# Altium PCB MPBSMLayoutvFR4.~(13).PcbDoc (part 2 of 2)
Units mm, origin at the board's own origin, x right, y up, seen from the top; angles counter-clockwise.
Board outline 131.7 x 110.39 mm, 4 copper layers (Top Layer, Power, GroundPlane, Bottom Layer), stack 2.286 mm thick; 156 components, 77 nets, 429 pads, 117 vias.
Unrouted connection lines stored in the file: 25.
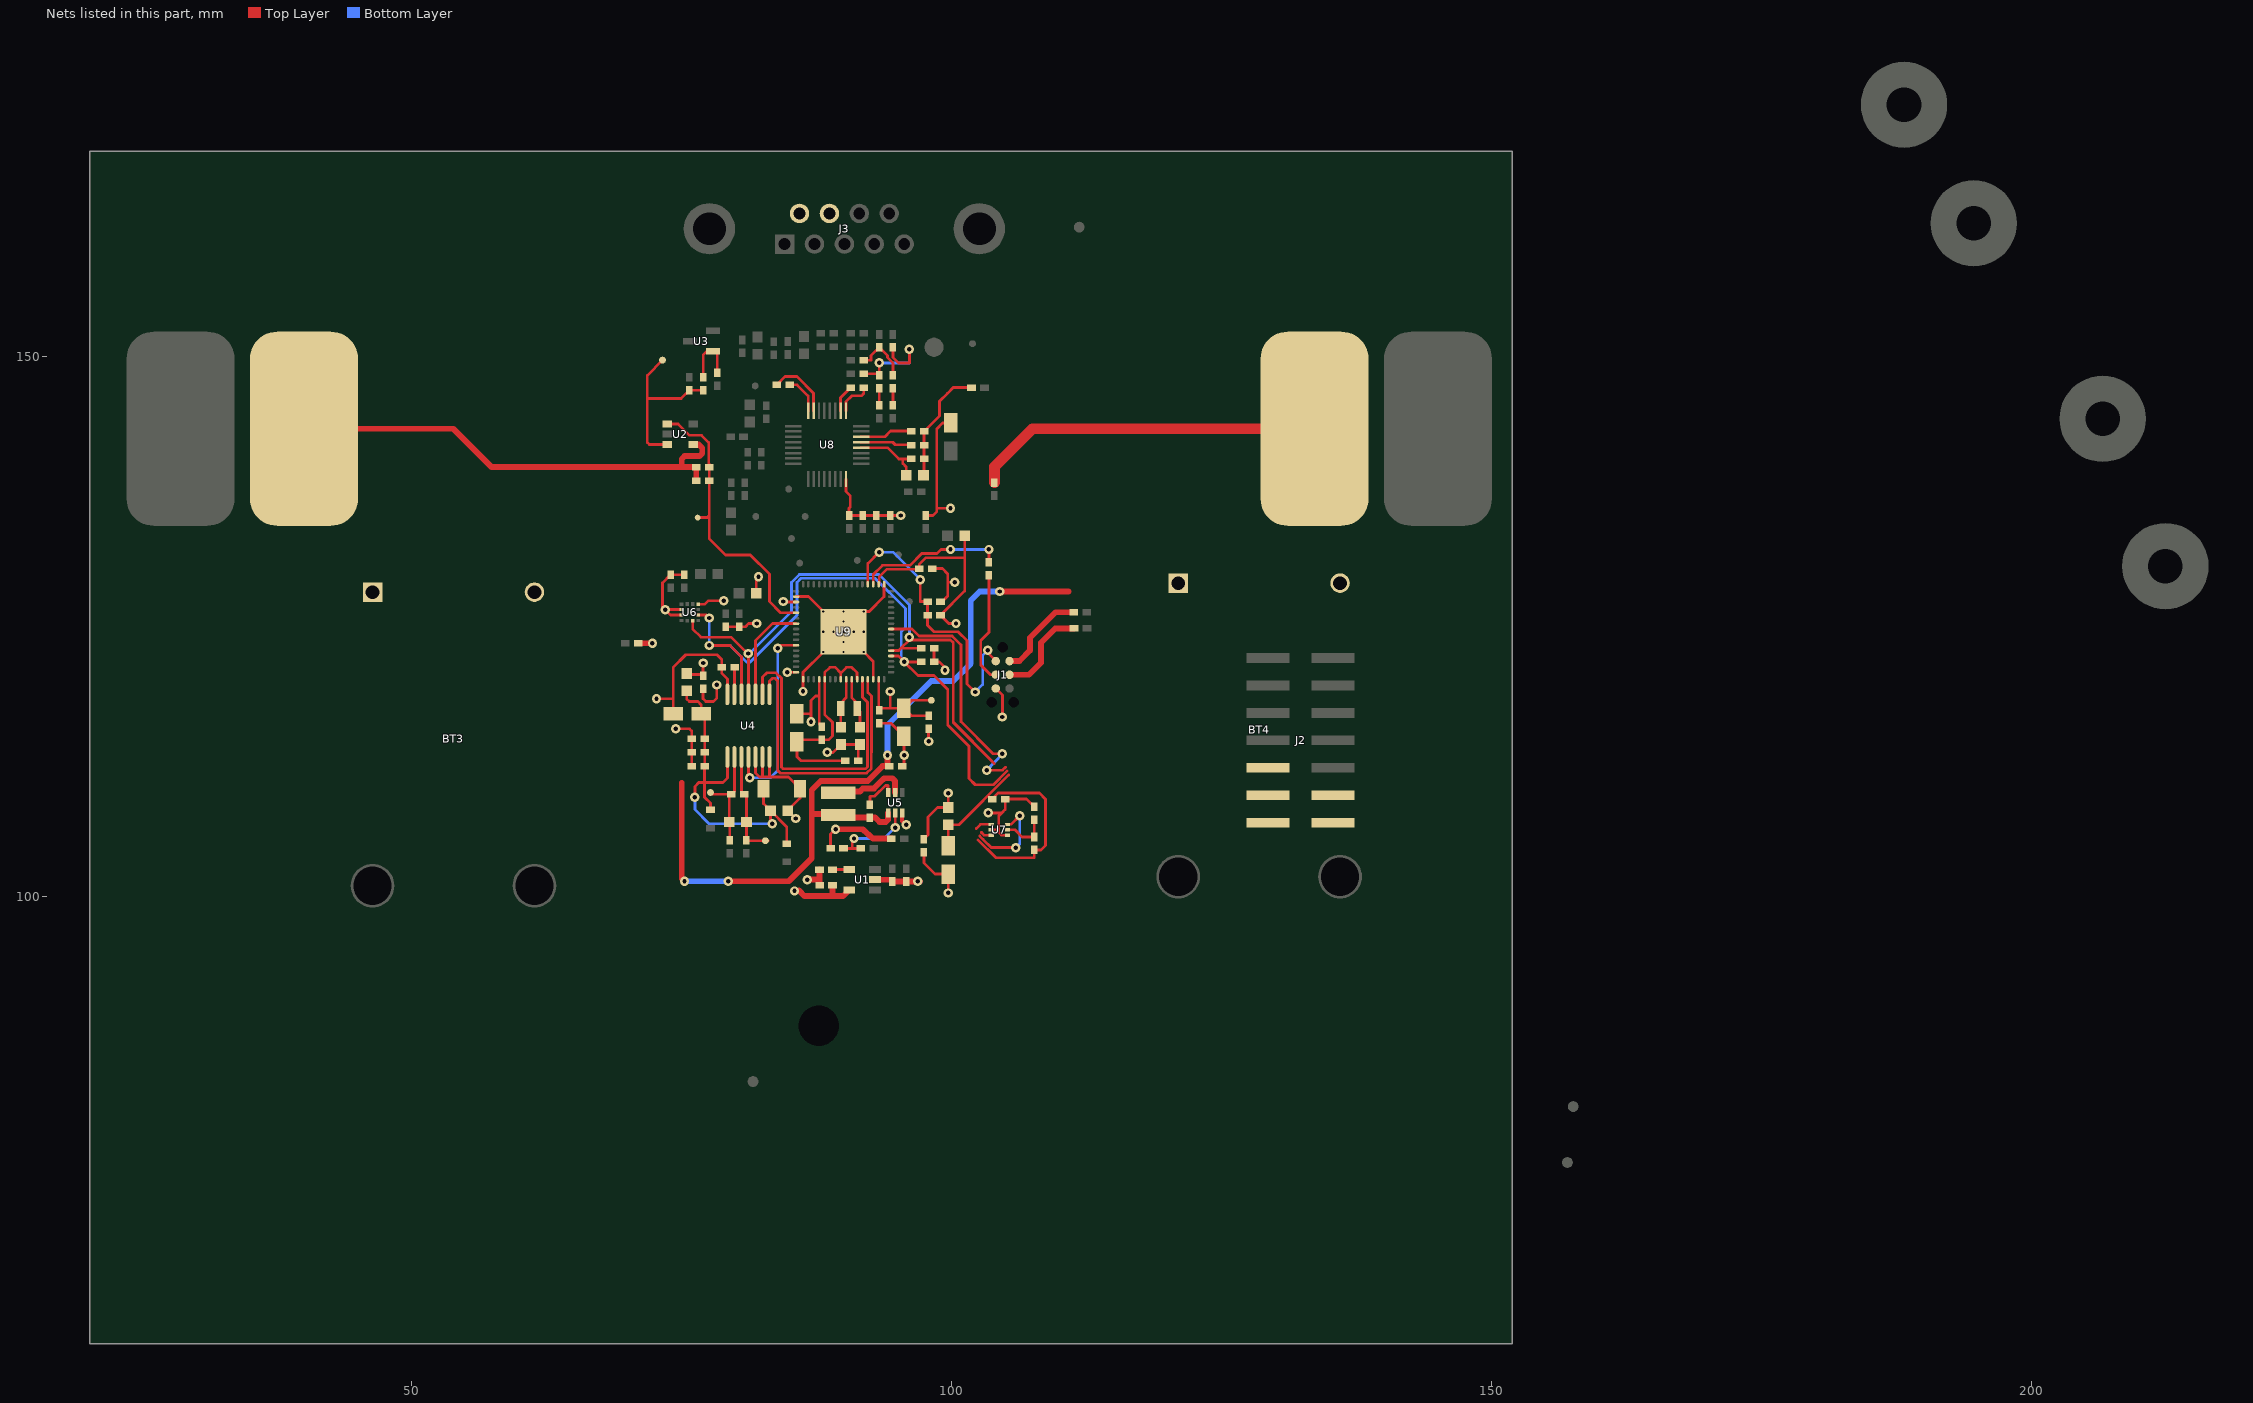
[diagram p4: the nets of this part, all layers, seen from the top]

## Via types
v1: diameter 0.864, hole 0.406, Top Layer to Bottom Layer, 104 vias
v2: diameter 0.5, hole 0.2, Top Layer to Bottom Layer, 13 vias

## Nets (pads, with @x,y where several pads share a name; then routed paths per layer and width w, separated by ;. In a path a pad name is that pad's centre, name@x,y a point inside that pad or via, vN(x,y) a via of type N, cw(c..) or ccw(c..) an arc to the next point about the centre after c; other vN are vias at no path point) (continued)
BOOST_INPUT: BT3.1 BT4.1 C34.1 L7.1 R16.1 U5.1 | length 73.3
  Top Layer w0.254: L7.1@89.536,107.681 L7.1@89.545,107.672 ; v1(94.082,113.132) v1@94.244,112.97
  Top Layer w0.5: 75.032,110.592 75.032,101.702 v1(75.286,101.448)
  Top Layer w0.54: v1(79.35,101.448) 84.938,101.448 87.071,103.581 87.071,109.906 87.909,110.744 92.253,110.744 93.624,112.116 C34.1@94.244,112.116 ; 87.071,107.696 L7.1@89.536,107.681 ; L7.1@89.755,107.35 R16.1@92.456,107.35 92.942,107.35 93.358,106.934 93.929,106.934 94.143,107.148 U5.1@94.143,107.762 ; C34.1@94.082,112.278 v1(94.082,113.132) ; v1(104.496,128.287) 110.845,128.287
  Bottom Layer w0.54: v1(75.286,101.448) v1(79.35,101.448) ; v1(94.082,113.132) 94.082,115.926 98.146,119.99 100.178,119.99 101.794,121.606 101.794,127.448 102.633,128.287 v1(104.496,128.287)
DVCC: 1.1 C1.1 C5.1 C6.1 C10.1 C14.1 C18.1 L1.1 L2.1 L3.1 L5.1 R1.1 R6.2 R31.1 R32.1 U1.5 U9.18 U9.35 U9.48 U9.63 | length 53
  Top Layer w0.254: L1.1@75.286,120.59 76.864,120.59 C10.1@76.887,120.613 ; C10.1@77.013,120.488 v1(77.013,121.666) ; L3.1@81.928,128.118 81.928,129.426 v1(82.144,129.642) ; v1@84.474,127.312 U9.35@85.618,127.312 ; v1(84.8,120.812) U9.48@85.618,120.812 ; U9.63@93.268,120.162 93.268,117.339 C6.1@93.32,117.288 ; U9.18@93.268,128.962 93.315,129.008 93.315,129.637 94.034,130.356 96.99,130.356 C18.1@97.038,130.404 97.038,130.82 97.638,131.42 101.194,131.42 ; C6.1@93.512,117.48 C1.1@95.606,117.48 ; 94.339,117.483 v1(94.339,119.027) ; C14.1@97.462,105.35 97.841,105.728 97.841,107.414 98.712,108.286 L2.1@99.703,108.286 v1(99.703,109.621) ; R1.1@97.892,116.78 96.306,116.78 C1.1@95.606,117.48 ; 1.1@98.146,118.212 96.338,118.212 C1.1@95.606,117.48 ; R32.1@98.4,123.038 R31.1@98.4,121.768 98.908,121.768 99.416,121.26 v1(99.416,121.006) ; v1(100.432,125.324) 99.762,125.324 R6.2@99,126.086 101.232,128.318 L5.1@101.232,133.452
  Top Layer w0.54: v1(85.471,100.559) v1@85.877,100.559 ; 85.903,100.584 86.411,100.076 88.997,100.076 ; C5.1@88.997,101.092 88.997,100.076 ; U1.5@90.545,100.65 89.971,100.076 88.997,100.076
  other v1: 84.43,127.356
EL_GSR1: C26.2 J3.7 R10.1 TP2.1 U2.4 | length 43.3
  Top Layer w0.254: U2.4@76.094,141.9 76.606,141.9
  Top Layer w0.54: TP2.1@40.056,143.358 53.873,143.358 57.429,139.802 R10.1@76.372,139.802 C26.2@76.372,138.532 ; 75.032,139.852 75.032,140.564 75.286,140.818 76.672,140.818 76.926,141.072 76.926,141.58 76.606,141.9
EL_GSR2: J3.6 R9.2 TP1.1 | length 32.6
  Top Layer w1: R9.2@103.988,138.37 103.988,139.827 107.518,143.358 TP1.1@133.629,143.358
GND: BT3.2 BT4.2 C1.2 C3.2 C4.2 C5.2 C6.2 C8.2 C9.2 C10.2 C11.2 C12.2 C13.2 C14.2 C15.2 C16.2 C17.2 C18.2 C19.2 C20.2 C21.2 C25.2 C27.2 C28.2 C29.1 C32.2 C33.2 C34.2 C35.2 C36.2 C37.2 C38.2 C41.2 C42.2 C58.2 C59.2 J1.6 J2.6 R2.1 R3.1 R17.1 U1.2 U4.5 U4.6 U4.7 U4.14 U5.3 U6.4 U6.8 U6.9 U7.2 U7.4 U8.24 U9.17 U9.34 U9.49 U9.62 U9.65 | length 145.9
  Top Layer w0.254: v1(72.695,118.364) 74.24,118.364 ; C9.2@74.24,116.942 74.24,118.364 ; v1(74.473,115.57) 75.743,115.57 75.956,115.357 C27.2@75.956,114.656 C11.2@75.956,113.386 C28.2@75.956,112.116 ; U6.9@75.019,126.111 73.99,126.111 v1(73.508,126.594) ; U6.8@75.019,126.611 73.525,126.611 v1(73.508,126.594) ; C37.2@75.286,129.847 C16.2@74.016,129.847 73.254,129.085 73.254,126.848 v1(73.508,126.594) ; U6.4@76.569,127.111 77.172,127.111 77.494,127.433 v1(78.914,127.433) ; C10.2@77.013,119.288 77.013,118.364 77.267,118.11 77.971,118.11 78.283,118.422 v1(78.283,119.634) ; C36.2@79.096,125.024 C17.2@80.366,125.024 80.921,125.024 81.221,125.324 v1(81.966,125.324) ; U4.14@79.26,118.764 79.26,120.193 78.75,120.704 C29.1@78.75,121.26 78.75,121.961 78.283,122.428 75.408,122.428 74.24,121.26 74.24,118.364 ; U4.5@81.86,112.964 81.86,111.484 82.245,111.1 83.16,111.1 ; 82.51,111.137 U4.6@82.51,112.964 ; U4.7@83.16,112.964 83.16,111.1 ; v1(85.594,107.266) 85.569,107.266 C33.2@84.844,107.991 85.998,109.145 C32.2@85.998,110.023 84.921,111.1 83.16,111.1 ; U9.34@85.618,127.812 86.768,127.812 v2(88.143,126.437) v2(90.018,124.562) ; v1(86.267,119.033) U9.49@86.267,120.162 86.267,120.811 v2(88.143,122.687) v2(90.018,124.562) ; v1(86.665,101.6) v1@86.677,101.613 ; v1(88.494,113.386) 89.04,113.386 89.764,114.11 C58.2@91.542,114.11 ; R17.1@88.818,104.496 88.818,105.812 v1(89.28,106.274) ; U8.24@90.244,138.704 90.244,137.544 90.626,137.162 90.626,136.099 90.526,135.999 C42.2@90.526,135.322 C41.2@91.796,135.322 C19.2@93.066,135.322 C20.2@94.336,135.322 v1@95.24,135.322 ; R2.1@91.38,112.624 C58.2@91.38,113.948 ; U9.62@92.768,120.162 92.768,121.811 v2(91.893,122.687) v2(90.018,124.562) ; C6.2@93.32,115.888 C6.2@93.32,116.088 94.398,116.088 C1.2@95.606,114.88 95.624,114.861 v1(95.624,113.132) 95.624,112.296 C34.2@95.444,112.116 C34.2@95.606,111.954 ; U9.17@93.769,128.962 93.769,127.805 92.401,126.437 v2(91.893,126.437) v2(90.018,124.562) ; C3.2@94.371,101.6 C3.2@94.544,101.428 ; v1(96.876,101.448) 96.876,101.194 v1@97.11,101.428 ; C14.2@97.462,104.15 97.462,103.147 98.488,102.122 C12.2@99.703,102.122 v1(99.703,100.374) ; C21.2@97.638,135.322 98.288,135.322 98.654,135.687 98.654,143.358 99.192,143.896 C15.2@99.924,143.896 C15.2@99.924,144.374 ; C18.2@98.238,130.404 99.162,130.404 99.67,129.896 99.67,129.134 ; 98.654,135.992 v1(99.924,135.992) ; C25.2@99,127.356 99.162,127.356 99.67,127.864 99.67,129.134 ; v1(100.305,129.134) 99.67,129.134 ; v1(103.424,107.783) 104.669,107.783 ; U7.2@103.703,106.221 104.373,106.221 ; J1.6@104.115,119.304 104.724,118.694 104.724,116.688 v1(104.699,116.662) ; U7.4@105.203,105.721 104.648,105.721 104.398,105.971 104.398,107.512 104.669,107.783 ; C38.2@107.681,108.352 106.965,109.068 C13.2@104.979,109.068 104.979,108.093 104.669,107.783
  Top Layer w0.354: U5.3@95.443,107.762 95.443,107.046 v1(95.809,106.68)
  Top Layer w0.54: R3.1@71.018,123.489 v1(72.321,123.489) ; v1@86.677,101.613 87.797,101.613 ; C5.2@87.797,101.092 87.797,101.613 ; C8.2@87.797,102.54 87.797,101.613 ; v1(89.28,106.274) 90.596,106.274 91.796,106.274 92.761,105.41 C35.2@94.497,105.41 ; U1.2@92.945,101.6 C3.2@94.371,101.6 ; C3.2@94.544,101.428 C4.2@95.814,101.428 v1@97.11,101.428
  other v1: 95.301,135.322
  other v2: 90.018,122.687 90.018,123.624 88.143,124.562 89.08,124.562 90.955,124.562 91.893,124.562 90.018,125.499 90.018,126.437
GSR_ANALOG_OUTPUT: 2.1 C26.1 R10.2 U2.1 U9.37 | length 26.9
  Top Layer w0.254: U2.1@73.694,143.8 74.7,143.8 75.752,142.748 76.869,142.748 77.53,142.088 77.53,140.14 77.572,140.098 R10.2@77.572,139.802 C26.1@77.572,138.532 77.572,135.23 ; 2.1@76.505,135.128 77.47,135.128 ; 77.47,135.23 77.572,135.23 ; U9.37@85.618,126.312 84.204,126.312 83.16,127.356 83.16,129.896 81.382,131.674 79.096,131.674 77.572,133.198 77.572,135.23
JTAG_TCK: J1.4 J2.4 R7.1 | length 10.4
  Top Layer w0.254: R7.1@103.48,129.804 103.48,124.511 102.718,123.749 102.718,121.463 103.607,120.574 J1.4@104.115,120.574
JTAG_TDO/TDI: C25.1 J1.2 J2.2 R6.1 U9.20 | length 28.1
  Top Layer w0.254: U9.20@92.268,128.962 92.268,130.876 v1(93.32,131.928) ; v1(97.13,129.388) 97.13,127.356 C25.1@97.8,127.356 R6.1@97.8,126.086 97.8,125.162 98.4,124.562 100.626,124.562 101.448,123.74 101.448,119.736 v1(102.21,118.974) ; v1(103.378,122.843) 103.378,122.58 J1.2@104.115,121.844
  Bottom Layer w0.254: v1(93.32,131.928) 94.59,131.928 v1(97.13,129.388) ; v1(102.21,118.974) 102.895,119.659 102.895,122.36 v1(103.378,122.843)
JTAG_TEST/SBWTCK: R7.2 U9.19 | length 13.7
  Top Layer w0.254: U9.19@92.768,128.962 92.768,129.852 93.626,130.71 96.166,130.71 97.257,131.801 98.652,131.801 99.033,132.182 v1(99.924,132.182) ; R7.2@103.48,131.004 v1(103.48,132.182)
  Bottom Layer w0.254: v1(99.924,132.182) v1(103.48,132.182)
JTAG_VCC_TARGET_IN: J1.3 J2.3 R5.1 | length 8.8
  Top Layer w0.54: J1.3@105.385,120.574 107.188,120.574 108.306,121.691 108.306,122.707 108.306,123.546 109.621,124.861 R5.1@111.357,124.861
JTAG_VCC_TOOL_OUT: J1.1 J2.1 R4.1 | length 8.5
  Top Layer w0.54: J1.1@105.385,121.844 106.299,121.844 107.29,122.834 107.29,124.003 109.652,126.365 R4.1@111.338,126.365
MSP_AVCC: C2.1 C7.1 R1.2 U9.52 | length 9.3
  Top Layer w0.254: C2.1@86.019,116.972 87,116.972 ; v1(87,116.21) 87,116.972 ; C7.1@87.767,115.982 87.767,118.618 ; U9.52@87.767,120.162 87.767,118.618 ; v1(97.892,114.402) R1.2@97.892,115.58 ; 87,116.972 87,118.191 87.427,118.618 87.767,118.618
MSP_AVSS: C2.2 C7.2 R2.2 U9.53 U9.56 U9.59 | length 20.5
  Top Layer w0.254: C2.2@85.7,114.372 85.7,112.979 86.055,112.624 R2.2@90.18,112.624 ; C2.2@85.892,114.564 C7.2@87.986,114.564 88.656,114.564 89.002,114.91 89.002,116.18 88.267,116.914 U9.53@88.267,120.162 88.267,120.779 88.748,121.26 89.256,121.26 89.76,120.756 ; U9.56@89.768,120.162 89.768,120.756 90.272,121.26 90.78,121.26 91.268,120.771 U9.59@91.268,120.162
MSP_LFXIN: C59.1 U9.57 Y1.1 | length 4.1
  Top Layer w0.254: C59.1@89.764,115.71 89.764,117.438 Y1.1@89.776,117.45 ; Y1.1@89.776,117.97 90.268,118.462 U9.57@90.268,120.162
MSP_LFXOUT: C58.1 U9.58 Y1.2 | length 4.3
  Top Layer w0.254: U9.58@90.768,120.162 90.768,118.477 Y1.2@91.276,117.97 ; Y1.2@91.276,117.45 91.542,117.184 C58.1@91.542,115.71
MSP_P1.0_INT: U4.10 U9.39 | length 9.4
  Top Layer w0.254: U4.10@81.86,118.764 81.86,123.749 ; 81.876,123.749 83.439,125.312 U9.39@85.618,125.312
MSP_P2.7_INT: U7.3 U9.9 | length 24.2
  Top Layer w0.254: U9.9@94.418,124.812 96.341,124.812 96.999,124.154 100.078,124.154 100.886,123.346 100.886,116.234 103.861,113.259 v1(104.724,113.259) ; 102.765,105.989 103.033,105.721 U7.3@103.703,105.721 ; v1@103.284,111.743 104.745,111.743 105.014,112.011
  Bottom Layer w0.254: v1(103.276,111.735) v1(104.724,113.259)
MSP_P4.0_INT: U4.9 U9.60 | length 28.4
  Top Layer w0.254: U4.9@82.51,118.764 82.51,120.356 82.906,120.752 83.772,120.752 84.276,120.248 84.276,112.016 84.43,111.862 92.05,111.862 92.234,112.046 92.234,113.506 92.244,113.516 92.244,114.704 92.234,114.713 92.234,115.106 92.244,115.116 92.244,116.304 92.234,116.313 92.234,118.027 91.768,118.493 U9.60@91.768,120.162
MSP_P4.1_INT: U4.8 U9.61 | length 27.8
  Top Layer w0.254: U4.8@83.16,118.764 83.16,119.99 83.414,120.244 83.668,120.244 83.922,119.99 83.922,111.718 84.186,111.454 92.15,111.454 ; 92.15,111.461 92.588,111.9 92.588,113.36 92.598,113.369 92.598,118.612 92.268,118.942 U9.61@92.268,120.162
MSP_P9.3_OUT: U4.4 U9.43 | length 18
  Top Layer w0.254: U4.4@81.21,112.964 81.21,111.169 v1(81.331,111.049) ; v1(83.922,123.038) 84.196,123.312 U9.43@85.618,123.312
  Bottom Layer w0.254: v1(81.331,111.049) 83.253,111.049 83.922,111.718 v1(83.922,123.038)
MSP_UCB0SCL_TMP103_SCL_RF430CL330HCPW_SCL: R32.2 U4.11 U6.12 U7.1 U9.5 | length 56.8
  Top Layer w0.254: U6.12@76.044,125.586 76.044,124.82 76.81,124.054 79.604,124.054 v1@81.16,122.497 ; U4.11@81.21,118.764 v1@81.21,122.447 ; U9.5@94.418,122.812 95.126,122.812 95.352,123.038 ; v1(96.114,124.054) v1@96.114,123.8 ; R32.2@97.038,123.038 95.352,123.038 ; 102.314,106.343 102.692,106.721 U7.1@103.703,106.721 ; 103.967,112.365 103.785,112.547 100.178,116.18 100.178,123.546 99.924,123.8 v1@96.114,123.8 ; 95.352,123.038 v1@96.114,123.8
  Bottom Layer w0.254: v1(81.202,122.539) 81.21,122.531 81.21,122.447 85.192,126.428 85.192,129.134 85.924,129.866 93.289,129.866 96.114,127.042 v1(96.114,124.054)
MSP_UCB0SDA_TMP103_SDA_RF430CL330HCPW_SDA: R31.2 U4.12 U6.2 U7.6 U9.4 | length 70.6
  Top Layer w0.254: U6.2@76.569,126.111 77.292,126.111 v1(77.572,125.832) ; v1(77.572,123.292) 79.518,123.292 80.577,122.233 80.577,118.78 U4.12@80.56,118.764 ; U9.4@94.418,122.312 95.098,122.312 v1(95.642,121.768) ; R31.2@97.2,121.768 v1(95.642,121.768) ; 102.618,105.635 102.921,105.332 102.929,105.332 103.691,104.57 v1(105.977,104.57) ; 105.16,111.657 103.892,110.388 102.21,110.388 101.638,110.96 101.638,113.957 99.67,115.926 99.67,119.228 98.4,120.498 96.912,120.498 v1(95.642,121.768) ; U7.6@105.203,106.721 105.537,106.721 v1(106.332,107.516)
  Bottom Layer w0.254: v1(77.572,125.832) v1(77.572,123.292) 79.518,123.292 81.042,121.768 81.382,121.768 85.7,126.086 85.7,129.134 86.078,129.512 92.941,129.512 95.76,126.694 95.76,124.97 95.352,124.562 95.352,122.058 v1(95.642,121.768) ; v1(105.977,104.57) 106.332,104.925 v1(106.332,107.516)
Net3_1: 3.1 R11.1 R12.2 U2.3 | length 15.6
  Top Layer w0.254: 71.846,146.152 74.983,146.152 R12.2@75.748,146.917 R11.1@77.018,146.917 ; 3.1@73.254,149.708 71.846,148.3 71.846,142.088 72.034,141.9 U2.3@73.694,141.9
Net4_1: 4.1 C30.1 C31.1 R13.1 U4.2 | length 9.9
  Top Layer w0.254: 4.1@77.694,109.676 77.855,109.515 C31.1@79.634,109.515 ; R13.1@79.472,105.255 79.472,106.903 C30.1@79.434,106.941 79.434,109.315 C31.1@79.634,109.515 ; U4.2@79.91,112.964 79.91,109.791 C31.1@79.634,109.515
Net5_1: 5.1 C30.2 C31.2 R14.1 U4.3 | length 9.9
  Top Layer w0.254: U4.3@80.56,112.964 80.56,109.788 C31.2@80.834,109.515 81.034,109.315 C30.2@81.034,106.941 81.034,105.293 81.131,105.197 5.1@83.028,105.197
NetC8_1: C8.1 U1.4 | length 1.6
  Top Layer w0.254: C8.1@88.992,102.54 89.002,102.55 U1.4@90.545,102.55
NetC29_2: C29.2 U4.13 | length 2.5
  Top Layer w0.254: U4.13@79.91,118.764 79.91,121.22 C29.2@79.95,121.26
NetC38_1: C38.1 R18.1 U7.5 | length 4.3
  Top Layer w0.254: U7.5@105.203,106.221 105.875,106.221 106.538,105.558 R18.1@107.681,105.558 C38.1@107.681,107.152
NetC43_1: C43.1 R19.2 R20.2 R21.2 R22.1 | length 10.9
  Top Layer w0.254: C43.1@97.476,139.094 R20.2@97.476,140.564 R21.2@97.476,141.834 97.476,141.876 R19.2@97.476,143.104 98.908,144.536 98.908,145.898 99.628,146.618 100.178,147.168 R22.1@101.864,147.168
NetC43_2: C43.2 R20.1 U8.28 | length 6.7
  Top Layer w0.254: U8.28@91.643,141.603 94.096,141.603 95.136,140.564 95.504,140.564 ; C43.2@95.822,139.04 95.822,139.818 95.504,140.135 95.504,140.564 ; R20.1@96.276,140.564 95.504,140.564
NetC45_1: C45.1 U8.2 | length 2.6
  Top Layer w0.254: U8.2@89.744,145.003 89.744,146.224 C45.1@90.688,147.168
NetC45_2: C45.2 U8.1 | length 3.4
  Top Layer w0.254: U8.1@90.244,145.003 90.244,145.87 90.78,146.406 91.681,146.406 91.888,146.612 C45.2@91.888,147.168
NetC46_2: C46.2 C48.2 C49.2 | length 10.4
  Top Layer w0.254: C46.2@91.888,148.45 C49.2@93.191,148.45 ; C49.2@93.32,148.322 v1(93.32,149.454) ; C48.2@94.59,150.886 94.595,150.88 94.595,149.967 95.109,149.454 96.114,149.454 v1(96.114,150.724)
  Bottom Layer w0.254: v1(93.32,149.454) 96.114,149.454 v1(96.114,150.724)
NetC47_1: C47.1 U8.8 | length 3.5
  Top Layer w0.254: C47.1@85.03,147.422 85.7,147.422 86.744,146.378 U8.8@86.744,145.003
NetC47_2: C47.2 U8.7 | length 6
  Top Layer w0.254: C47.2@83.83,147.422 84.592,148.184 85.7,148.184 87.244,146.64 U8.7@87.244,145.003
NetC49_1: C49.1 R26.1 | length 1.6
  Top Layer w0.254: R26.1@93.32,145.528 C49.1@93.32,147.122
NetC52_2: C52.2 C53.2 C54.2 | length 5.3
  Top Layer w0.254: C54.2@91.888,149.708 92.558,149.708 92.558,150.124 C52.2@93.32,150.886 94.082,150.124 94.082,149.962 94.59,149.454 C53.2@94.59,148.322
NetC53_1: C53.1 R27.1 | length 1.6
  Top Layer w0.254: R27.1@94.59,145.528 C53.1@94.59,147.122
NetL7_2: L7.2 U5.5 | length 5.5
  Top Layer w0.254: 92.862,110.033 92.862,110.084
  Top Layer w0.54: L7.2@90.983,109.752 91.515,109.752 91.796,110.033 92.862,110.033 ; 92.862,110.084 93.443,110.664 93.777,110.998 94.539,110.998 94.793,110.744 U5.5@94.793,109.662
NetR8_1: R8.1 R11.2 U3.1 | length 5.5
  Top Layer w0.254: R11.2@77.018,148.117 77.018,150.17 77.384,150.536 78.334,150.536 R8.1@78.334,148.53
NetR15_1: R15.1 R17.2 U5.2 | length 8.1
  Top Layer w0.254: R17.2@90.018,104.496 90.815,104.496 ; v1(90.983,105.41) 90.815,105.242 90.815,104.496 ; R15.1@91.612,104.496 90.815,104.496 ; v1(94.793,106.426) U5.2@94.793,107.762
  Bottom Layer w0.254: v1(90.983,105.41) 93.777,105.41 v1(94.793,106.426)
NetR16_2: R16.2 U5.6 | length 3.5
  Top Layer w0.254: R16.2@92.456,108.55 92.456,109.271 92.507,109.322 92.888,109.322 93.893,110.327 94.132,110.327 94.132,109.672 U5.6@94.143,109.662
NetR19_1: R19.1 U8.30 | length 4.9
  Top Layer w0.254: U8.30@91.643,142.603 93.835,142.603 94.378,143.146 R19.1@96.276,143.146
NetR21_1: R21.1 U8.29 | length 4.7
  Top Layer w0.254: U8.29@91.643,142.103 94.574,142.103 94.802,141.876 R21.1@96.276,141.876
RF430_DVCC: C9.1 C11.1 C27.1 C28.1 C32.1 C33.1 D1.1 D2.1 L1.2 U4.1 | length 34
  Top Layer w0.254: 75.489,118.512 75.489,118.338 75.735,118.092 76.523,118.092 76.84,117.775 C9.1@76.84,116.942 C9.1@77.064,117.166 ; v1(76.251,109.22) 76.251,110.236 76.606,110.592 77.15,110.592 ; C28.1@77.156,112.116 C11.1@77.156,113.386 C27.1@77.156,114.656 C9.1@77.156,116.626 ; C28.1@77.247,112.024 77.15,111.926 77.15,110.592 ; D1.1@77.694,108.079 77.694,108.691 77.15,109.235 77.15,110.592 ; U4.1@79.26,112.964 79.26,111.01 78.842,110.592 77.15,110.592 ; C32.1@82.598,110.023 82.598,108.637 C33.1@83.244,107.991 ; v1(83.414,106.782) 83.244,106.951 C33.1@83.244,107.991 ; D2.1@84.76,104.989 84.76,106.475 C33.1@83.244,107.991
  Bottom Layer w0.254: v1(76.251,109.22) 76.251,108.102 77.572,106.782 v1(83.414,106.782)
TMP_DVCC: C12.1 C13.1 L2.2 R18.2 | length 27
  Top Layer w0.254: C12.1@99.703,104.722 L2.2@99.703,106.686 100.69,106.686 105.307,111.303 ; 102.472,105.281 104.123,103.63 107.681,103.63 R18.2@107.681,104.358 108.305,104.358 108.715,104.768 108.715,109.049 108.147,109.618 104.329,109.618 C13.1@103.779,109.068
pads on no net: BT3.3 BT3.4 BT4.3 BT4.4 FID1.1 FID2.1 FID3.1 H1.0 H2.0 H3.0 H4.0 H5.1 H6.1 H7.1 H8.1 H9.0 H10.0 H11.0 H12.0 J1.5 J1.MH1 J1.MH2 J1.MH3 J2.5 J2.7 J2.8 J2.9 J2.10 J2.11 J2.12 J2.13 J2.14 J3.3 J3.5 J3.8 J3.9 U3.3 U6.10 U8.17 U9.1 U9.2 U9.3 U9.6 U9.7 U9.8 U9.10 U9.11 U9.12 U9.13 U9.15 U9.21 U9.22 U9.23 U9.24 U9.36 U9.40 U9.41 U9.42 U9.44 U9.45 U9.46 U9.47 U9.50 U9.51 U9.54 U9.55 U9.64
copper on no net: | length 0.5
  Top Layer w0.254: 104.445,124.206 v1(104.445,124.714)

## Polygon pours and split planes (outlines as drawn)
DVCC on Power (split plane): 102.334,142.288 102.334,131.727 101.699,131.092 78.59,131.092 77.955,131.727 77.955,133.144 79.149,134.338 93.066,134.338 93.115,134.348 93.157,134.376 98.237,139.456 98.265,139.498 98.275,139.548 98.275,142.796 98.684,143.205 101.417,143.205
DVCC on Power (split plane): 87.51,117.065 87.856,116.61 87.856,112.624 87.866,112.574 87.894,112.532 87.936,112.504 87.986,112.494 95.952,112.494 96.001,112.504 96.043,112.532 96.967,113.456 96.995,113.498 97.005,113.548 97.005,115.796 98.768,115.796 98.768,115.57 98.768,113.937 98.308,113.477 97.031,112.2 96.568,111.737 86.727,111.737 86.083,112.41 86.083,116.653 86.498,117.089
DVCC on Power (split plane): 90.65,154.534 90.609,146.998 81.89,147.043 81.865,147.038 81.841,147.033 81.84,147.033 81.819,147.019 81.799,147.006 81.798,147.005 81.784,146.984 81.77,146.964 81.77,146.963 81.765,146.939 81.76,146.914 81.76,143.104 81.77,143.054 81.798,143.012 81.84,142.984 81.89,142.974 86.586,142.974 86.586,141.201 83.414,141.201 83.364,141.191 83.322,141.163 83.294,141.121 83.284,141.072 83.284,135.359 77.142,135.359 77.142,139.09 77.132,139.14 77.104,139.182 74.907,141.379 74.907,145.59 77.924,148.607 79.063,148.607 79.087,148.612 79.112,148.616 79.112,148.617 79.133,148.631 79.154,148.644 79.154,148.645 79.168,148.665 79.182,148.686 79.182,148.687 79.187,148.711 79.192,148.736 79.224,154.658 90.65,154.658
DVCC on Power (split plane): 151.407,158.471 151.407,59.159 20.729,59.159 20.729,168.527 151.407,168.527
ADS_AVSS on GroundPlane (split plane): 151.407,158.471 151.407,128.806 102.085,128.806 102.085,137.008 102.075,137.057 102.047,137.099 102.005,137.127 101.956,137.137 98.908,137.137 98.858,137.127 98.816,137.099 98.788,137.057 98.778,137.008 98.778,135.765 96.446,135.765 96.446,136.398 96.436,136.448 96.408,136.49 96.366,136.518 96.317,136.527 89.378,136.527 89.362,136.524 89.347,136.524 89.338,136.52 89.328,136.518 89.315,136.509 89.301,136.503 77.631,127.993 20.729,128.018 20.729,168.527 151.407,168.527
GND on GroundPlane (split plane): 101.826,128.676 101.836,128.627 101.864,128.585 101.906,128.557 101.956,128.547 151.407,128.547 151.407,59.159 20.729,59.159 20.729,127.759 77.673,127.734 77.723,127.744 77.765,127.772 77.768,127.776 77.784,127.784 89.42,136.269 96.187,136.269 96.187,135.636 96.197,135.586 96.225,135.544 96.267,135.516 96.317,135.507 98.908,135.507 98.957,135.516 98.999,135.544 99.027,135.586 99.037,135.636 99.037,136.878 101.826,136.878

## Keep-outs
Keep-Out Layer:
  text ".Layer_Name" at 157.226,108.306 h1.52

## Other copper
Top Layer:
  text ".Layer_Name" at 157.226,156.566 h1.52
Bottom Layer:
  text ".Layer_Name" at 157.226,154.026 h1.52
  text "SVN:" at 49.644,114.91 h1.52 r90
  text ".VersionControl_RevNumber" at 49.644,107.823 h1.52 r90
  text "UL94V-0" at 55.677,69.774 h1.52 r90
Power (plane layer: these items are gaps in the copper):
  rectangle: 74.778,69.952 100.178,99.67
  lines w0.254: 98.898,115.57 98.898,115.926 ; 98.898,115.926 98.494,115.926 96.876,115.926 96.876,113.548 95.952,112.624 88.205,112.624 87.986,112.624 87.986,116.654 87.576,117.193 86.444,117.219 85.954,116.705 85.954,112.358 86.672,111.608 92.14,111.608 96.622,111.608 97.122,112.108 98.4,113.386 98.898,113.884 98.898,115.926 ; 74.778,141.326 77.013,139.09 77.013,135.23 81.186,135.23 83.414,135.23 83.414,141.072 86.716,141.072 86.716,143.104 81.89,143.104 81.89,146.914 90.738,146.868 90.78,154.534 90.78,154.788 79.096,154.788 79.063,148.736 77.87,148.736 74.778,145.644 74.778,141.326 ; 77.826,131.674 77.826,133.198 79.096,134.468 93.066,134.468 98.146,139.548 98.146,142.85 98.63,143.334 101.471,143.334 102.464,142.342 102.464,131.674 101.752,130.962 78.537,130.962 77.826,131.674
GroundPlane (plane layer: these items are gaps in the copper):
  rectangle: 74.778,69.952 100.178,99.67
  lines w0.254: 20.041,127.889 77.673,127.864 ; 77.707,127.888 89.378,136.398 96.317,136.398 96.317,135.636 98.908,135.636 98.908,137.008 101.956,137.008 101.956,128.676 151.714,128.676

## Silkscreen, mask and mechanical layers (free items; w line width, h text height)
Top Overlay:
  region: 96.317,77.724 96.317,85.344 93.777,85.344 93.777,77.724
  lines w1: 73.863,70.891 100.99,70.891 100.99,98.222 73.863,98.222 73.863,70.891
  lines w2: 20.93,133.325 44.729,133.325 150.241,133.325 ; 48.92,60.96 48.92,132.918 48.92,167.716 ; 125.628,61.646 125.628,167.157
  text "GSR" at 130.048,153.289 h4
  text "ECG" at 141.427,153.238 h4
  text "ECG" at 24.689,152.806 h4
  text "GSR" at 37.338,152.756 h4
  text "GND" at 46.584,131.318 h1.02
  text "VCC" at 60.096,129.845 h1.02
  text ".Layer_Name" at 157.226,128.626 h1.52
  text "JTAG" at 106.731,126.009 h1.02
  text "BAT" at 110.541,122.987 h1.02
  text "VCC" at 61.976,121.361 h1.02
  text "GND" at 46.838,121.158 h1.02
  text "FOR DEMO PURPOSES ONLY" at 76.479,94.259 h1.02
  text "MPBSM" at 80.061,91.44 h1.02
  text "REV A" at 80.061,89.916 h1.02
  text "TI" at 92.151,87.884 h1.52
  text "©" at 94.793,87.63 h2.67
  text ".CopyrightYear" at 85.141,77.724 h1.52
  text "MADE IN U.S." at 78.791,75.438 h1.52
  text "NFC Antenna" at 80.543,68.504 h2
  text "-" at 50.901,67.666 h1.52 r90
  text "Place phone here" at 52.908,62.84 h10
Bottom Overlay:
  text ".Layer_Name" at 157.226,126.086 h1.52
Top Paste:
  text ".Layer_Name" at 157.226,123.546 h1.52
Bottom Paste:
  text ".Layer_Name" at 157.226,121.006 h1.52
Top Solder:
  text ".Layer_Name" at 157.226,118.466 h1.52
  text ".Layer_Name" at 157.226,115.926 h1.52
Bottom Solder:
  text ".Layer_Name" at 157.226,113.386 h1.52
Drill Guide:
  text ".Layer_Name" at 157.226,110.846 h1.52
M1 Board Outline:
  lines w0.254: 75.286,58.257 101.575,58.257
  text ".Layer_Name" at 157.226,151.486 h1.52
M2 Board Dimensions:
  rectangle: 17.577,32.982 20.752,36.157
  rectangle: 20.752,29.807 30.277,32.982
  lines w0.178: 17.577,32.982 42.977,32.982 ; 20.752,29.807 20.752,36.157 ; 23.927,29.807 23.927,36.157 ; 30.277,29.807 30.277,36.157 ; 36.627,29.807 36.627,36.157 ; 17.577,29.807 42.977,29.807 42.977,36.157 17.577,36.157 17.577,29.807
  text ".Layer_Name" at 18.034,37.338 h1.52
M3 3D STEP Top:
  text ".Layer_Name" at 157.226,148.946 h1.52
M4 3D STEP Bottom:
  text ".Layer_Name" at 157.226,146.406 h1.52
M5 Assembly Top:
  lines w0.254: 10.16,16.607 177.8,16.607 ; 10.16,21.772 177.851,21.772 ; 10.16,26.937 10.16,11.443 111.887,11.443 177.851,11.443 177.851,26.937 10.173,26.937 10.173,11.443 50.19,11.443 ; 72.771,11.443 72.771,26.937 ; 104.953,21.772 104.953,26.937 ; 126.289,21.772 126.289,26.937 ; 142.088,11.278 142.088,16.43
  text "COMPONENTS MARKED 'DNP' SHOULD NOT BE POPULATED." at 46.876,32.144 h1.52
  text "ASSEMBLY VARIANT:" at 46.863,29.21 h1.52
  text ".VariantName" at 73.177,29.21 h1.52
  text "PCB VIEWED FROM TOP SIDE" at 11.773,23.58 h1.52
  text "BOARD #:" at 74.676,23.58 h1.52
  text ".PRJ_Number" at 88.532,23.58 h1.52
  text "REV:" at 109.982,23.58 h1.52
  text ".PCB_Rev" at 117.386,23.58 h1.52
  text "SVN REV:" at 131.267,23.58 h1.52
  text ".VersionControl_RevNumber" at 144.12,23.58 h1.52
  text "IGNORE ->" at 11.773,18.428 h1.52
  text "PLOT NAME =" at 11.773,13.199 h1.52
  text ".plot_File_Name" at 32.233,13.199 h1.52
  text "GENERATED    :" at 74.727,13.199 h1.52
  text ".Print_Date" at 96.812,13.199 h1.52
  text ".Print_Time" at 115.329,13.199 h1.52
  text "TEXAS INSTRUMENTS" at 147.447,13.199 h1.52
M6 Assembly Bottom:
  lines w0.254: 10.147,21.759 177.838,21.759 ; 10.198,16.595 177.838,16.595 ; 45.91,11.265 45.91,16.417 ; 61.709,21.759 61.709,26.924 ; 83.045,21.759 83.045,26.924 ; 115.227,11.43 115.227,26.924 ; 137.808,11.43 177.825,11.43 177.825,26.924 10.147,26.924 10.147,11.43 76.111,11.43 177.838,11.43 177.838,26.924
  text "COMPONENTS MARKED 'DNP' SHOULD NOT BE POPULATED." at 172.568,32.156 h1.52
  text ".VariantName" at 146.05,29.21 h1.52
  text "ASSEMBLY VARIANT:" at 172.441,29.21 h1.52
  text ".VersionControl_RevNumber" at 43.878,23.567 h1.52
  text "SVN REV:" at 56.731,23.567 h1.52
  text ".PCB_Rev" at 70.612,23.567 h1.52
  text "REV:" at 78.016,23.567 h1.52
  text ".PRJ_Number" at 99.466,23.567 h1.52
  text "BOARD #:" at 113.322,23.567 h1.52
  text "PCB VIEWED FROM BOTTOM SIDE" at 176.225,23.567 h1.52
  text "IGNORE ->" at 82.292,18.428 h1.52
  text "TEXAS INSTRUMENTS" at 40.551,13.187 h1.52
  text ".Print_Time" at 72.669,13.187 h1.52
  text ".Print_Date" at 91.186,13.187 h1.52
  text "GENERATED    :" at 113.271,13.187 h1.52
  text ".plot_File_Name" at 155.766,13.187 h1.52
  text "PLOT NAME =" at 176.225,13.187 h1.52
M9 Title Sheet:
  drawing of 57 lines, arcs and shapes, not listed
  text "1" at 36.369,243.091 h1.78
  text "2" at 99.758,243.091 h1.78
  text "3" at 162.988,243.091 h1.78
  text "4" at 226.657,243.091 h1.78
  text "5" at 290.131,243.091 h1.78
  text "6" at 353.758,243.091 h1.78
  text "A" at 6.998,214.058 h1.78
  text "A" at 382.918,214.058 h1.78
  text "B" at 6.998,153.606 h1.78
  text "B" at 382.918,153.606 h1.78
  text ".Layer_Name" at 157.226,143.866 h1.52
  text "C" at 6.998,93.281 h1.78
  text "C" at 382.918,93.281 h1.78
  text "PROJECT TITLE:" at 305.702,46.012 h1.14
  text ".PRJ_Title" at 306.972,42.626 h1.78
  text "DESIGNED FOR:" at 305.702,38.367 h1.14
  text ".PRJ_Customer" at 306.972,34.811 h1.78
  text "D" at 6.998,33.084 h1.78
  text "D" at 382.918,33.084 h1.78
  text "FILE NAME:" at 305.702,30.747 h1.14
  text ".PCB_File_Name_No_Path" at 306.972,27.699 h1.78
  text "Texas Instruments (TI) and/or its licensors do not warrant the accuracy or completeness of this specification" at 179.476,23.588 h1.14
  text "ENGINEER:" at 305.702,23.381 h1.14
  text "LAYOUT BY:" at 343.929,23.381 h1.14
  text "or any information contained therein. TI and/or its licensors do not warrant that this design will meet" at 178.334,20.726 h1.14
  text ".PRJ_Engineer" at 306.972,19.444 h1.78
  text ".PCB_Layout" at 345.211,19.444 h1.78
  text "the specifications, will be suitable for your application or fit for any particular purpose, or will operate in" at 178.334,17.865 h1.14
  text "ALTIUM DESIGNER VERSION:" at 343.929,15.507 h1.14
  text "an implementation. TI and/or its licensors do not warrant that the design is production worthy. You should" at 178.334,15.003 h1.14
  text "completely validate and test your design implementation to confirm the system functionality for your application." at 179.476,12.141 h1.14
  text ".print_Scale" at 306.972,12.12 h1.78
  text ".Application_BuildNumber" at 345.211,12.12 h1.78
  text "1" at 36.369,6.871 h1.78
  text "2" at 99.758,6.871 h1.78
  text "3" at 162.988,6.871 h1.78
  text "4" at 226.657,6.871 h1.78
  text "5" at 290.131,6.871 h1.78
  text "6" at 353.758,6.871 h1.78
M10 Fab Notes:
  drawing of 185 lines, arcs and shapes, not listed
  text "DESIGN INFORMATION" at 332.055,190.348 h1.52
  text "MIN. TRACK WIDTH:" at 315.683,185.776 h1.52
  text "8" at 343.527,185.776 h1.52
  text "MIL" at 347.458,185.776 h1.52
  text "MIN. CLEARANCE:" at 315.683,182.423 h1.52
  text "0.2" at 342.003,182.423 h1.52
  text "mm" at 347.458,182.423 h1.52
  text "MIN. VIA PAD SIZE:" at 315.683,179.07 h1.52
  text "24" at 342.766,179.07 h1.52
  text "MIL" at 347.458,179.07 h1.52
  text "0.05mm (2MIL)" at 333.336,175.471 h1.52
  text "MINIMUM ANNULAR RING" at 307.32,175.362 h1.52
  text "EXTERNAL" at 351.319,175.362 h1.52
  text "PER" at 312.4,172.364 h1.52
  text "IPC-D-275 CLASS 2 LEVEL C" at 317.988,172.364 h1.52
  text "MIL, HOLES" at 355.789,169.512 h1.52
  text "+/-" at 345.821,169.494 h1.52
  text "+/-" at 367.513,169.494 h1.52
  text "REGISTRATION TOLERANCES:" at 307.32,169.367 h1.52
  text "METAL" at 337.795,169.367 h1.52
  text "5" at 352.43,169.367 h1.52
  text "3" at 373.588,169.367 h1.52
  text "MIL" at 376.541,169.367 h1.52
  text "MATERIAL:" at 305.421,164.047 h1.52
  text "FR-4 High Tg" at 330.477,160.482 h1.52
  text "FR-408" at 316.115,160.265 h1.52
  text "X" at 326.579,160.265 h1.52
  text "OTHER" at 353.91,160.265 h1.52
  text "62 MIL (1.6mm) +/-10%" at 324.245,156.132 h1.52
  text "THICKNESS:" at 307.32,156.023 h1.52
  text "X" at 320.99,156.023 h1.52
  text "OTHER" at 356.882,156.023 h1.52
  text "TOLERANCE:" at 307.32,152.01 h1.52
  text "X" at 328.639,152.01 h1.52
  text "ANSI IPC-6012 TYPE 3 CLASS 2" at 333.387,152.01 h1.52
  text "OTHER +/-" at 333.387,148.047 h1.52
  text "BOW & TWIST:" at 307.32,144.06 h1.52
  text "X" at 328.639,144.06 h1.52
  text "ANSI IPC-6012 TYPE 3 CLASS 2" at 333.387,144.06 h1.52
  text ".Layer_Name" at 157.226,141.326 h1.52
  text "OTHER +/-" at 333.387,140.034 h1.52
  text "DRILLING:" at 305.421,136.516 h1.52
  text "REFERENCE:" at 307.32,133.544 h1.52
  text "X" at 323.785,133.544 h1.52
  text "AS SHOWN" at 328.535,133.544 h1.52
  text "X" at 346.671,133.544 h1.52
  text "NC_DRILL FILES" at 350.151,133.544 h1.52
  text "PTH MIN COPPER THICKNESS:" at 307.32,129.531 h1.52
  text "X" at 341.616,129.531 h1.52
  text "1MIL" at 345.096,129.531 h1.52
  text "OTHER" at 357.72,129.531 h1.52
  text "BOARD FINISH:" at 305.421,125.492 h1.52
  text "SILKSCREEN:" at 309.364,122.495 h1.52
  text "X" at 333.463,122.495 h1.52
  text "TOP" at 336.663,122.495 h1.52
  text "X" at 346.417,122.495 h1.52
  text "BOTTOM" at 349.643,122.495 h1.52
  text "SILKSCREEN COLOR:" at 310.634,118.26 h1.52
  text "X" at 333.436,118.253 h1.52
  text "WHITE" at 336.663,118.253 h1.52
  text "OTHER" at 349.643,118.253 h1.52
  text "SOLDER RESIST COLOR:" at 309.364,113.935 h1.52
  text "GREEN" at 327.011,109.892 h1.52
  text "BLUE" at 342.023,109.892 h1.52
  text "OTHER" at 355.688,109.892 h1.52
  text "X" at 323.785,109.644 h1.52
  text "IMMERSION GOLD (ENIG)" at 332.371,105.103 h1.52
  text "ENEPIG" at 366.344,105.02 h1.52
  text "SURFACE FINISH:" at 305.421,104.994 h1.52
  text "X" at 327.622,104.994 h1.52
  text "IMM. TIN/SILVER OR EQUIV" at 313.792,101.007 h1.52
  text "OTHER" at 350.151,101.007 h1.52
  text "ARRAY/PANEL:" at 305.421,96.46 h1.52
  text "CUT AND TRIM PER MECH LAYER 1" at 332.371,96.351 h1.52
  text "N.C. ROUTE" at 332.371,92.498 h1.52
  text "X" at 349.617,92.498 h1.52
  text "V. SCORE" at 354.367,92.498 h1.52
  text "CERTIFICATION:" at 305.421,89.018 h1.52
  text "MATERIALS AND WORKMANSHIP FOR ALL PCBS" at 323.836,89.018 h1.52
  text "TO MEET OR EXCEED THE REQUIREMENTS OF:" at 323.836,86.529 h1.52
  text "X" at 314.349,83.061 h1.52
  text "ANSI IPC-A-600F CLASS ->" at 317.88,83.061 h1.52
  text "X" at 359.512,83.061 h1.52
  text "2" at 362.533,83.061 h1.52
  text "1" at 354.532,83.023 h1.52
  text "3" at 371.525,83.023 h1.52
  text "X" at 314.402,79.01 h1.52
  text "UL 94V-0" at 317.88,79.01 h1.52
  text "X" at 335.026,79.01 h1.52
  text "RoHS" at 338.505,79.01 h1.52
  text "OTHER" at 354.873,79.01 h1.52
  text "PER ORDER" at 364.958,79.01 h1.52
  text "ADDITIONAL REQUIREMENTS:" at 305.193,75.302 h1.52
  text "MICROSECTION:" at 307.092,72.381 h1.52
  text "YES" at 330.098,72.381 h1.52
  text "REQUIRED" at 352.208,68.542 h1.52
  text "NONE" at 340.486,68.469 h1.52
  text "X" at 348.982,68.469 h1.52
  text "PER ORDER" at 367.245,68.469 h1.52
  text "BARE BOARD ELEC. TEST:" at 307.092,68.342 h1.52
  text "MANUFACTURER'S UL:" at 307.092,64.354 h1.52
  text "METAL" at 349.422,64.373 h1.52
  text "X" at 358.953,64.364 h1.52
  text "SILK" at 362.419,64.373 h1.52
  text "RAIL" at 336.702,64.245 h1.52
M11 Gerber Information:
  lines w0.254: 10.16,16.607 177.8,16.607 ; 10.16,21.772 177.851,21.772 ; 10.16,26.937 10.16,11.443 111.887,11.443 177.851,11.443 177.851,26.937 10.173,26.937 10.173,11.443 50.19,11.443 ; 72.771,11.443 72.771,26.937 ; 104.953,21.772 104.953,26.937 ; 126.289,21.772 126.289,26.937 ; 142.088,11.278 142.088,16.43
  text "ALL ARTWORK VIEWED FROM TOP SIDE" at 11.773,23.58 h1.52
  text "BOARD #:" at 74.676,23.58 h1.52
  text ".PRJ_Number" at 88.532,23.58 h1.52
  text "REV:" at 109.982,23.58 h1.52
  text ".PCB_Rev" at 117.386,23.58 h1.52
  text "SVN REV:" at 131.267,23.58 h1.52
  text ".VersionControl_RevNumber" at 144.12,23.58 h1.52
  text "LAYER NAME =" at 11.773,18.428 h1.52
  text "PLOT NAME =" at 11.773,13.199 h1.52
  text ".plot_File_Name" at 32.233,13.199 h1.52
  text "GENERATED    :" at 74.727,13.199 h1.52
  text ".Print_Date" at 96.812,13.199 h1.52
  text ".Print_Time" at 115.329,13.199 h1.52
  text "TEXAS INSTRUMENTS" at 147.447,13.199 h1.52
M12 Stackup:
  lines w0.152: 305.105,221.59 369.875,221.59 ; 305.105,224.241 369.875,224.241 ; 303.581,209.271 ccw(c304.444,209.271) 304.444,208.407 370.535,208.407 ccw(c370.535,209.271) 371.399,209.271 371.399,227.203 ccw(c370.535,227.203) 370.535,228.067 304.444,228.067 ccw(c304.444,227.203) 303.581,227.203 303.581,209.271
  text "The Stackup Legend below this is static." at 311.34,232.118 h1.52
  text "If you change the stackup, update the Legend." at 311.594,229.832 h1.52
  text "Layer Stack Up Detail for: Ref_Design.PcbDoc" at 305.105,225.072 h1.45
  text "Layer" at 305.105,223.251 h0.61
  text "Gerber" at 327.858,223.251 h0.61
  text "Copper" at 342.172,223.251 h0.61
  text "Dielectric" at 357.481,223.251 h0.61
  text "Name" at 305.105,222.032 h0.61
  text "Document" at 327.858,222.032 h0.61
  text "Thickness" at 342.172,222.032 h0.61
  text "Material" at 357.481,222.032 h0.61
  text "Top Solder Mask" at 305.105,219.67 h0.86
  text "(.GTS)" at 327.858,219.67 h0.86
  text "Solder Resist" at 357.481,219.67 h0.86
  text ".Layer_Name" at 284.988,218.186 h1.52
  text "Top Layer" at 305.105,217.213 h0.86
  text "(.GTL)" at 327.858,217.213 h0.86
  text "1.4mil" at 342.172,217.213 h0.86
  text "FR-4" at 357.481,215.984 h0.86
  text "Bottom Layer" at 305.105,214.755 h0.86
  text "(.GBL)" at 327.858,214.755 h0.86
  text "1.4mil" at 342.172,214.755 h0.86
  text "Bottom Solder Mask" at 305.105,212.298 h0.86
  text "(.GBS)" at 327.858,212.298 h0.86
  text "Solder Resist" at 357.481,212.298 h0.86
M13 Component Bodies Top:
  text ".Layer_Name" at 157.226,138.786 h1.52
M14 Component Bodies Bottom:
  text ".Layer_Name" at 157.226,136.246 h1.52
M15 Courtyards Top:
  text ".Layer_Name" at 157.226,133.706 h1.52
M16 Courtyards Bottom:
  text ".Layer_Name" at 157.226,131.166 h1.52
Drill Drawing:
  text ".Layer_Name" at 157.226,105.766 h1.52

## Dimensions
145.059,143.358 to 151.917,158.471 on M2 Board Dimensions
28.626,143.358 to 20.218,169.037 on M2 Board Dimensions
125.628,61.646 to 151.917,58.649 on M2 Board Dimensions
20.218,58.649 to 48.92,60.96 on M2 Board Dimensions
133.629,143.358 to 145.059,143.358 on M2 Board Dimensions
28.626,143.358 to 40.056,143.358 on M2 Board Dimensions
17.577,29.807 to 42.977,29.807 on M2 Board Dimensions
75.794,72.492 to 99.162,72.492 on M2 Board Dimensions
99.162,97.13 to 99.162,72.492 on M2 Board Dimensions
99.67,71.984 to 125.628,61.646 on M2 Board Dimensions
48.92,60.96 to 75.235,71.984 on M2 Board Dimensions
48.92,60.96 to 125.628,61.646 on M2 Board Dimensions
